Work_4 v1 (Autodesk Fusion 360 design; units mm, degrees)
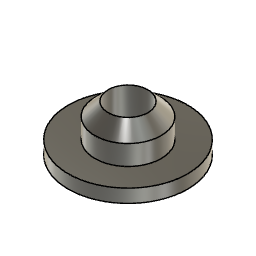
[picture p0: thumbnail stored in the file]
sketch "Sketch1" plane through (0, 0, 0) normal (0, 1, 0) x axis (1, 0, 0)
  line L1 (15, -10) -> (15, -45)
  line L2 (45, -10) -> (15, -10)
  line L3 (45, -20) -> (45, -10)
  line L4 (25, -20) -> (45, -20)
  line L5 (25, -35) -> (25, -20)
  line L6 (15, -45) -> (25, -35)
  point P1 (0, 0)
  vertical L1
  perpendicular L1 L2
  perpendicular L2 L3
  perpendicular L3 L4
  perpendicular L4 L5
  dimension "d1" distance P1 L2 = 10
  dimension "d2" distance P1 L1 = 15
  dimension "d3" distance P1 L4 = 20
  dimension "d4" distance P1 L5 = 25
  dimension "d5" distance P1 L3 = 45
  dimension "d6" distance P1 L6 = 42.4264
revolve "Revolve1" sketch "Sketch1" AlongAngle 360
